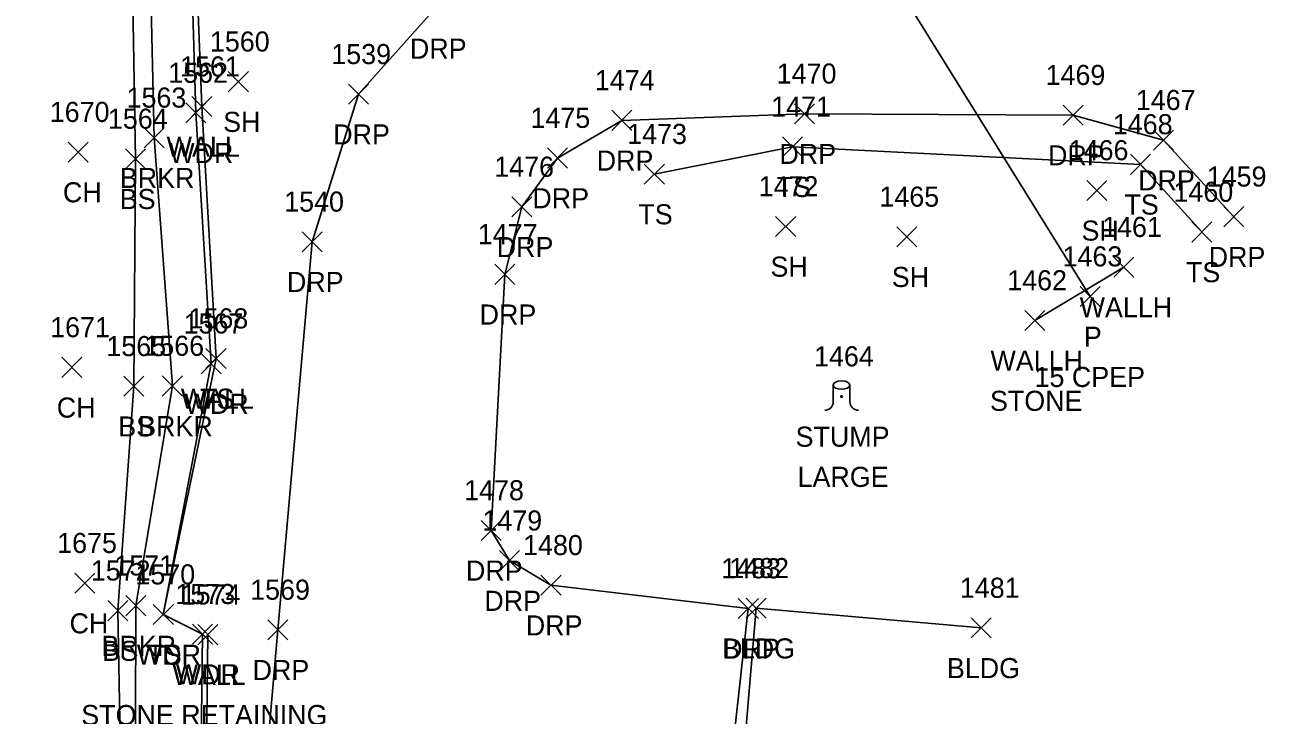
# Model space of a CAD drawing. Extents: x 1651305 to 1654558, y 539481 to 548441.
# Drawn here: x 1654364.2 to 1654487.7, y 544748.1 to 544816.8 of the extents above; entities that cross this region are included whole.
import ezdxf

# ---------------------------------------------------------------- set-up
doc = ezdxf.new("R2010")
doc.units = 0
for name, color, linetype in [('D_A', 7, 'Continuous'), ('D_C', 7, 'Continuous'), ('D_I', 7, 'Continuous'), ('D_TIC', 7, 'Continuous'), ('DCP', 7, 'Continuous'), ('DHW', 7, 'Continuous'), ('L_A', 7, 'Continuous'), ('L_C', 7, 'Continuous'), ('L_I', 7, 'Continuous'), ('L_TIC', 7, 'Continuous'), ('LAWA', 7, 'Continuous'), ('LAWE', 7, 'Continuous'), ('LBC', 7, 'Continuous'), ('LELB', 7, 'Continuous'), ('LTS', 7, 'Continuous'), ('LW', 7, 'Continuous'), ('R_A', 7, 'Continuous'), ('R_I', 7, 'Continuous'), ('R_TIC', 7, 'Continuous'), ('RDP', 7, 'Continuous')]:
    doc.layers.add(name, color=color, linetype=linetype)

msp = doc.modelspace()

# ---------------------------------------------------------------- linework, layer by layer
at = {"layer": 'D_TIC'}
for points in [[(1654472.67, 544791.67), (1654474.67, 544793.67)], [(1654474.67, 544791.67), (1654472.67, 544793.67)], [(1654469.3, 544788.74), (1654471.3, 544790.74)], [(1654471.3, 544788.74), (1654469.3, 544790.74)], [(1654463.79, 544786.36), (1654465.79, 544788.36)], [(1654465.79, 544786.36), (1654463.79, 544788.36)]]:
    msp.add_lwpolyline(points, dxfattribs=at)
at = {"layer": 'DCP'}
msp.add_lwpolyline([(1654470.3, 544789.74), (1654438.22, 544841.41)], dxfattribs=at)
at = {"layer": 'DHW'}
msp.add_lwpolyline([(1654473.67, 544792.67), (1654464.79, 544787.36)], dxfattribs=at)
at = {"layer": 'L_TIC'}
for points in [[(1654384.47, 544810.13), (1654386.47, 544812.13)], [(1654386.47, 544810.13), (1654384.47, 544812.13)], [(1654380.23, 544807.02), (1654382.23, 544809.02)], [(1654382.23, 544807.02), (1654380.23, 544809.02)], [(1654380.84, 544807.65), (1654382.84, 544809.65)], [(1654382.84, 544807.65), (1654380.84, 544809.65)], [(1654376.08, 544804.55), (1654378.08, 544806.55)], [(1654378.08, 544804.55), (1654376.08, 544806.55)], [(1654439.67, 544803.65), (1654441.67, 544805.65)], [(1654441.67, 544803.65), (1654439.67, 544805.65)], [(1654368.52, 544803.12), (1654370.52, 544805.12)], [(1654370.52, 544803.12), (1654368.52, 544805.12)], [(1654374.22, 544802.45), (1654376.22, 544804.45)], [(1654376.22, 544802.45), (1654374.22, 544804.45)], [(1654425.9, 544800.93), (1654427.9, 544802.93)], [(1654427.9, 544800.93), (1654425.9, 544802.93)], [(1654474.31, 544801.9), (1654476.31, 544803.9)], [(1654476.31, 544801.9), (1654474.31, 544803.9)], [(1654469.96, 544799.31), (1654471.96, 544801.31)], [(1654471.96, 544799.31), (1654469.96, 544801.31)], [(1654438.98, 544795.72), (1654440.98, 544797.72)], [(1654440.98, 544795.72), (1654438.98, 544797.72)], [(1654451.06, 544794.69), (1654453.06, 544796.69)], [(1654453.06, 544794.69), (1654451.06, 544796.69)], [(1654480.44, 544795.17), (1654482.44, 544797.17)], [(1654482.44, 544795.17), (1654480.44, 544797.17)], [(1654382.25, 544782.57), (1654384.25, 544784.57)], [(1654384.25, 544782.57), (1654382.25, 544784.57)], [(1654382.25, 544782.57), (1654384.25, 544784.57)], [(1654384.25, 544782.57), (1654382.25, 544784.57)], [(1654367.9, 544781.69), (1654369.9, 544783.69)], [(1654369.9, 544781.69), (1654367.9, 544783.69)], [(1654381.76, 544782.06), (1654383.76, 544784.06)], [(1654383.76, 544782.06), (1654381.76, 544784.06)], [(1654374.07, 544779.81), (1654376.07, 544781.81)], [(1654376.07, 544779.81), (1654374.07, 544781.81)], [(1654377.9, 544779.84), (1654379.9, 544781.84)], [(1654379.9, 544779.84), (1654377.9, 544781.84)], [(1654369.17, 544760.21), (1654371.17, 544762.21)], [(1654371.17, 544760.21), (1654369.17, 544762.21)], [(1654374.25, 544757.97), (1654376.25, 544759.97)], [(1654376.25, 544757.97), (1654374.25, 544759.97)], [(1654436.05, 544757.71), (1654438.05, 544759.71)], [(1654438.05, 544757.71), (1654436.05, 544759.71)], [(1654372.47, 544757.47), (1654374.47, 544759.47)], [(1654374.47, 544757.47), (1654372.47, 544759.47)], [(1654377, 544757.08), (1654379, 544759.08)], [(1654379, 544757.08), (1654377, 544759.08)], [(1654377, 544757.08), (1654379, 544759.08)], [(1654379, 544757.08), (1654377, 544759.08)], [(1654380.89, 544755.13), (1654382.89, 544757.13)], [(1654382.89, 544755.13), (1654380.89, 544757.13)], [(1654381.44, 544755.08), (1654383.44, 544757.08)], [(1654383.44, 544755.08), (1654381.44, 544757.08)], [(1654458.45, 544755.75), (1654460.45, 544757.75)], [(1654460.45, 544755.75), (1654458.45, 544757.75)]]:
    msp.add_lwpolyline(points, dxfattribs=at)
at = {"layer": 'LAWA'}
msp.add_lwpolyline([(1654379.78, 544856.85), (1654381.23, 544808.02), (1654382.76, 544783.06), (1654378, 544758.08), (1654381.89, 544756.13), (1654381.66, 544736.71), (1654380.9, 544705.78), (1654381.56, 544700.36), (1654376.77, 544678.51), (1654368.51, 544665.19)], dxfattribs=at)
at = {"layer": 'LAWE'}
msp.add_lwpolyline([(1654375.94, 544856.31), (1654377.08, 544805.55), (1654378.9, 544780.84), (1654375.25, 544758.97), (1654375.2, 544735.18), (1654374.98, 544710.3), (1654371.32, 544695.81), (1654368.77, 544679.57), (1654363.1, 544667.03), (1654358.05, 544658.63), (1654352.36, 544650.11), (1654344.9, 544634.32), (1654334.88, 544605.42), (1654326.4, 544588.83), (1654321.27, 544565.19), (1654313.3, 544530.3), (1654300.22, 544501.74), (1654283.17, 544465.47), (1654261.06, 544441.26)], dxfattribs=at)
at = {"layer": 'LBC'}
msp.add_lwpolyline([(1654459.45, 544756.75), (1654437.05, 544758.71), (1654435.44, 544739.9), (1654436.44, 544740.01), (1654435.88, 544732.82)], dxfattribs=at)
at = {"layer": 'LELB'}
for points in [[(1654374.34, 544855.82), (1654375.22, 544803.45), (1654375.07, 544780.81), (1654373.47, 544758.47), (1654373.91, 544734.87), (1654373.92, 544712.91), (1654369.62, 544696.27), (1654366.92, 544680.67), (1654362.17, 544668.56), (1654357.64, 544659.43), (1654350.7, 544650.57), (1654343.25, 544636.93), (1654333.62, 544607.27), (1654325.31, 544589.17), (1654319.06, 544565.66), (1654310.74, 544531.11), (1654298.27, 544501.75), (1654282.29, 544466.34), (1654260.01, 544442.91)], [(1654481.44, 544796.17), (1654475.31, 544802.9), (1654440.67, 544804.65), (1654426.9, 544801.93)], [(1654383.25, 544783.57), (1654378, 544758.08)]]:
    msp.add_lwpolyline(points, dxfattribs=at)
at = {"layer": 'LTS'}
for p, q in [((1654444.72, 544780.93), (1654444.72, 544779.26)), ((1654446.38, 544780.76), (1654446.38, 544780.93)), ((1654446.38, 544780.93), (1654446.38, 544779.26)), ((1654445.55, 544779.79), (1654445.55, 544779.79)), ((1654445.55, 544779.79), (1654445.55, 544779.79)), ((1654445.55, 544779.76), (1654445.55, 544779.76))]:
    msp.add_line(p, q, dxfattribs=at)
msp.add_circle((1654445.55, 544779.79), 0.0833, dxfattribs=at)
for centre, start, end in [((1654443.88, 544779.26), 270, 360), ((1654447.22, 544779.26), 180, 270)]:
    msp.add_arc(centre, 0.833, start, end, dxfattribs=at)
msp.add_ellipse((1654445.55, 544780.93), major_axis=(-0.833, 0), ratio=0.5, dxfattribs=at)
at = {"layer": 'LW'}
for points in [[(1654380.71, 544876.04), (1654380.84, 544875.27), (1654379.86, 544872.51), (1654379.95, 544856.82), (1654381.84, 544808.65), (1654383.25, 544783.57)], [(1654382.44, 544756.08), (1654382.2, 544736.39), (1654381.66, 544705.93)]]:
    msp.add_lwpolyline(points, dxfattribs=at)
at = {"layer": 'R_TIC'}
for points in [[(1654396.43, 544808.88), (1654398.43, 544810.88)], [(1654398.43, 544808.88), (1654396.43, 544810.88)], [(1654422.67, 544806.28), (1654424.67, 544808.28)], [(1654424.67, 544806.28), (1654422.67, 544808.28)], [(1654440.87, 544806.94), (1654442.87, 544808.94)], [(1654442.87, 544806.94), (1654440.87, 544808.94)], [(1654467.62, 544806.8), (1654469.62, 544808.8)], [(1654469.62, 544806.8), (1654467.62, 544808.8)], [(1654476.6, 544804.31), (1654478.6, 544806.31)], [(1654478.6, 544804.31), (1654476.6, 544806.31)], [(1654416.26, 544802.53), (1654418.26, 544804.53)], [(1654418.26, 544802.53), (1654416.26, 544804.53)], [(1654412.71, 544797.67), (1654414.71, 544799.67)], [(1654414.71, 544797.67), (1654412.71, 544799.67)], [(1654483.62, 544796.69), (1654485.62, 544798.69)], [(1654485.62, 544796.69), (1654483.62, 544798.69)], [(1654391.82, 544794.19), (1654393.82, 544796.19)], [(1654393.82, 544794.19), (1654391.82, 544796.19)], [(1654411.02, 544790.95), (1654413.02, 544792.95)], [(1654413.02, 544790.95), (1654411.02, 544792.95)], [(1654409.65, 544765.46), (1654411.65, 544767.46)], [(1654411.65, 544765.46), (1654409.65, 544767.46)], [(1654411.48, 544762.45), (1654413.48, 544764.45)], [(1654413.48, 544762.45), (1654411.48, 544764.45)], [(1654415.61, 544760), (1654417.61, 544762)], [(1654417.61, 544760), (1654415.61, 544762)], [(1654435.26, 544757.69), (1654437.26, 544759.69)], [(1654437.26, 544757.69), (1654435.26, 544759.69)], [(1654388.4, 544755.56), (1654390.4, 544757.56)], [(1654390.4, 544755.56), (1654388.4, 544757.56)]]:
    msp.add_lwpolyline(points, dxfattribs=at)
at = {"layer": 'RDP'}
for points in [[(1654473.04, 544948.78), (1654475.1, 544921.55), (1654479.17, 544878.59), (1654482.23, 544843.6), (1654480.57, 544836.69), (1654476.02, 544831.84), (1654469.83, 544828.85), (1654462.34, 544827.89), (1654428.87, 544826.99), (1654415.21, 544824.36), (1654405.08, 544818.42), (1654397.43, 544809.88), (1654392.82, 544795.19), (1654389.4, 544756.56), (1654387.7, 544737.06)], [(1654484.62, 544797.69), (1654477.6, 544805.31), (1654468.62, 544807.8), (1654441.87, 544807.94), (1654423.67, 544807.28), (1654417.26, 544803.53), (1654413.71, 544798.67), (1654412.02, 544791.95), (1654410.65, 544766.46), (1654412.48, 544763.45), (1654416.61, 544761), (1654436.26, 544758.69), (1654433.29, 544731.91), (1654435.78, 544731.7)]]:
    msp.add_lwpolyline(points, dxfattribs=at)

# ---------------------------------------------------------------- texts
at = {"layer": 'D_A'}
for s, p in [('WALLH', (1654469.26, 544787.67)), ('P', (1654469.68, 544784.74)), ('WALLH', (1654460.38, 544782.36))]:
    msp.add_text(s, height=2, dxfattribs=at).set_placement(p)
at = {"layer": 'D_C'}
for s, p in [('15 CPEP', (1654464.77, 544780.74)), ('STONE', (1654460.33, 544778.36))]:
    msp.add_text(s, height=2, dxfattribs=at).set_placement(p)
at = {"layer": 'D_I'}
for s, p in [('1461', (1654471.5, 544795.67)), ('1463', (1654467.56, 544792.74)), ('1462', (1654462.05, 544790.36))]:
    msp.add_text(s, height=2, dxfattribs=at).set_placement(p)
at = {"layer": 'L_A'}
for s, p in [('SH', (1654383.96, 544806.13)), ('WALL', (1654378.33, 544803.65)), ('WDR', (1654378.59, 544803.02)), ('BRKR', (1654373.67, 544800.55)), ('TS', (1654439.08, 544799.65)), ('CH', (1654368, 544799.12)), ('BS', (1654373.66, 544798.45)), ('TS', (1654473.72, 544797.9)), ('TS', (1654425.31, 544796.93)), ('SH', (1654469.45, 544795.31)), ('SH', (1654438.47, 544791.72)), ('TS', (1654479.85, 544791.17)), ('SH', (1654450.55, 544790.69)), ('WALL', (1654379.74, 544778.57)), ('TS', (1654381.66, 544778.57)), ('CH', (1654367.39, 544777.69)), ('WDR', (1654380.12, 544778.06)), ('BS', (1654373.51, 544775.81)), ('BRKR', (1654375.49, 544775.84)), ('STUMP', (1654440.97, 544774.79)), ('CH', (1654368.66, 544756.21)), ('BRKR', (1654371.84, 544753.97)), ('BS', (1654371.91, 544753.47)), ('WDR', (1654375.36, 544753.08)), ('TS', (1654376.41, 544753.08)), ('BLDG', (1654433.64, 544753.71)), ('BLDG', (1654456.04, 544751.75)), ('WALL', (1654378.92, 544751.08)), ('WDR', (1654379.25, 544751.13))]:
    msp.add_text(s, height=2, dxfattribs=at).set_placement(p)
at = {"layer": 'L_C'}
for s, p in [('LARGE', (1654441.17, 544770.79)), ('STONE RETAINING', (1654369.83, 544747.08))]:
    msp.add_text(s, height=2, dxfattribs=at).set_placement(p)
at = {"layer": 'L_I'}
for s, p in [('1560', (1654382.64, 544814.13)), ('1562', (1654378.49, 544811.02)), ('1561', (1654379.67, 544811.65)), ('1563', (1654374.34, 544808.55)), ('1670', (1654366.69, 544807.12)), ('1471', (1654438.54, 544807.65)), ('1564', (1654372.48, 544806.45)), ('1468', (1654472.57, 544805.9)), ('1473', (1654424.2, 544804.93)), ('1466', (1654468.17, 544803.31)), ('1472', (1654437.29, 544799.72)), ('1465', (1654449.32, 544798.69)), ('1460', (1654478.61, 544799.17)), ('1567', (1654380.02, 544786.06)), ('1568', (1654380.51, 544786.57)), ('1568', (1654380.51, 544786.57)), ('1671', (1654366.73, 544785.69)), ('1565', (1654372.33, 544783.81)), ('1566', (1654376.11, 544783.84)), ('1464', (1654442.81, 544782.79)), ('1675', (1654367.43, 544764.21)), ('1572', (1654370.78, 544761.47)), ('1571', (1654373.12, 544761.97)), ('1482', (1654434.36, 544761.71)), ('1570', (1654375.22, 544761.08)), ('1570', (1654375.22, 544761.08)), ('1573', (1654379.2, 544759.13)), ('1574', (1654379.74, 544759.08)), ('1481', (1654457.33, 544759.75))]:
    msp.add_text(s, height=2, dxfattribs=at).set_placement(p)
at = {"layer": 'R_A'}
for p in [(1654402.56, 544813.42), (1654394.92, 544804.88), (1654421.16, 544802.28), (1654439.36, 544802.94), (1654466.11, 544802.8), (1654475.09, 544800.31), (1654414.75, 544798.53), (1654411.2, 544793.67), (1654482.11, 544792.69), (1654390.31, 544790.19), (1654409.5, 544786.95), (1654408.14, 544761.46), (1654409.97, 544758.45), (1654414.1, 544756), (1654433.75, 544753.69), (1654386.89, 544751.56)]:
    msp.add_text('DRP', height=2, dxfattribs=at).set_placement(p)
at = {"layer": 'R_I'}
for s, p in [('1539', (1654394.73, 544812.88)), ('1470', (1654439.09, 544810.94)), ('1469', (1654465.87, 544810.8)), ('1474', (1654420.98, 544810.28)), ('1467', (1654474.86, 544808.31)), ('1475', (1654414.57, 544806.53)), ('1476', (1654410.96, 544801.67)), ('1459', (1654481.92, 544800.69)), ('1540', (1654390.04, 544798.19)), ('1477', (1654409.32, 544794.95)), ('1478', (1654407.96, 544769.46)), ('1479', (1654409.78, 544766.45)), ('1480', (1654413.83, 544764)), ('1483', (1654433.56, 544761.69)), ('1569', (1654386.65, 544759.56))]:
    msp.add_text(s, height=2, dxfattribs=at).set_placement(p)

doc.saveas('drawing.dxf')
